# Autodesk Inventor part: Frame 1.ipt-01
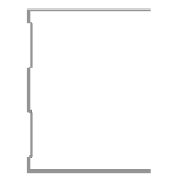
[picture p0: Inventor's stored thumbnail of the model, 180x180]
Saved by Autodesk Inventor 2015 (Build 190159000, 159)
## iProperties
Created: 2015-04
Part Number: Frame 1.ipt-01
Material: Aluminum 6061
Document SubType Name: Modeling
Standard: Unnamed
Designer: suporte
Language: en-US
Size Designation: (Unnamed 1)
Categories: <MemberInstance><Categories><Category DisplayName="Structural Shapes" InternalName="089c4875-fa83-4c05-b084-43b9cc11f5ed" Mnemonic="GRDR"><CategoryParameter Dis
Density: 2.7 g/cm^3
Appearance: Aluminum - Flat
IsCustomPart: 1
_CCFamilyMember: 1
_CCFamilyDisplayName: Frame 1
_FrameMemberDoc: Frame Member File
_Version: 15.0.0
_GetPNFromCC: 1
Author: suporte
G_L: 470,645 mm
G_W: 70,000 mm
G_H: 75,000 mm
+C6D07C4E-F784-4905-9E85-D001DAC4732C+CUTDETAIL1: Miter 67,49 deg
+9BC56BD3-3601-4756-9CD3-DFE412EE9504+CUTDETAIL2: Miter 67,51 deg
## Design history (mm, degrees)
node "Start Plane"
node "End Plane"
sketch "Sketch"
  geometry: L1 (34.6, 37.5)-(34.6, 36.7); L2 (34.6, 36.7)-(-34.6, 36.7); L3 (-34.6, -36.7)-(34.6, -36.7); L4 (34.6, -36.7)-(34.6, -37.5); L5 (34.6, -37.5)-(-35.4, -37.5); L6 (-35.4, 37.5)-(34.6, 37.5); L7 (-34.6, 36.7)-(-34.6, 31.7); L8 (-34.6, 31.7)-(-33.4, 30.5); L9 (-33.4, 30.5)-(-33.4, 10.746); L10 (-33.4, 10.746)-(-34.6, 9.546); L11 (-34.6, 9.546)-(-34.6, -9.546); L12 (-34.6, -9.546)-(-33.4, -10.746); L13 (-33.4, -10.746)-(-33.4, -30.5); L14 (-33.4, -30.5)-(-34.6, -31.7); L15 (-34.6, -31.7)-(-34.6, -36.7); L16 (-35.4, -37.5)-(-35.4, -31.369); L17 (-35.4, -31.369)-(-34.2, -30.169); L18 (-34.2, -30.169)-(-34.2, -11.077); L19 (-34.2, -11.077)-(-35.4, -9.877); L20 (-35.4, -9.877)-(-35.4, 9.877); L21 (-35.4, 9.877)-(-34.2, 11.077); L22 (-34.2, 11.077)-(-34.2, 30.169); L23 (-34.2, 30.169)-(-35.4, 31.369); L24 (-35.4, 31.369)-(-35.4, 37.5); L25 (-35.4, 0)-(30.37, 0); 3 further points
  constraints: 50 end point, 10 point on line, 9 parallel, 5 perpendicular, 4 equal length, 3 midpoint, 3 vertical, 2 vertical alignment, 1 collinear, 1 horizontal, 1 horizontal alignment
  dimensions: "d3" = 0.8 distance of L1.start L1.end; "d5" = 75 distance between parallel lines of L5 L6; "d6" = 0.8 distance between parallel lines of L24 L7; "d7" = 0.8 distance between parallel lines of L8 L23; "d8" = 0.8 distance between parallel lines of L22 L9; "d9" = 0.8 distance between parallel lines of L17 L14; "d10" = 0.8 distance between parallel lines of L13 L18; "d11" = 0.8 distance between parallel lines of L12 L19; "d12" = 0.8 distance between parallel lines of L21 L10; "d13" = 5 distance of L2.end L7.end; "d15" = 135 deg angle of L9 L8; "d16" = 2 distance between parallel lines of L24 L9; "d17" = 70 distance of L6.start L1.start
extrude "Body" join sketch "Sketch" stored distance "d24" = 0.13; taper "d25" = 0 deg
node "Driven Length"
  sketch "Sketch8"
    geometry: L1 (0, 0)-(10, 0) reference
    constraints: 2 end point, 1 horizontal
  workplane "Work Plane6"
  sketch "Sketch9"
    geometry: L1 (-2, -36.226)-(12, -36.226) reference; L2 (-2, 434.419)-(12, 434.419) reference
    dimensions: "d27" = 470.64466 distance between parallel lines of L1 L2 (derived)
workplane "Work Plane7"
split "Split1"
workplane "Work Plane8"
split "Split2"
body "Solid1"
other parameters: "tamanho" = 398.15728, "G_OFFSET_START" = 36.22585 [user parameter; used in 1 equation term], "G_OFFSET_END" = 36.26152 [user parameter; used in 1 equation term], "d22" = -36.22585 (= -G_OFFSET_START), "d23" = 434.41881 (= tamanho + G_OFFSET_END), "G_L" = 470.64466 (= d27) [user parameter], "d32" = 90 deg
